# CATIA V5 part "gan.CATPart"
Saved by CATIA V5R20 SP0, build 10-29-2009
Part number: 杆
Bounding box of the stored display mesh (mm): x -8.5 to 10, y -89.091 to 471.474, z -537.91 to 111.108
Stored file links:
  E:\3D工程制图作业\Part1.CATPart
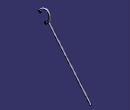
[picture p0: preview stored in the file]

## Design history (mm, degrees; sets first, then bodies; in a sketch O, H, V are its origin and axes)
Body1 (main body)
  Sketch1 on yz-plane, origin (0, 0, 0), H (0, 1, 0), V (0, 0, 1)
    line L1 (16.6642, 5.1613) -> (464.9558, -532.4581)
    point P2 (464.9558, -532.4581)
    spline S1 through (16.6642, 5.1613) (28.9221, 65.5082) (8.9158, 97.5942) (-34.5762, 97.5941) (-72.8491, 60.3051)
    point P3 (16.6642, 5.1613)
    length L1 = 700
    coincidence: P3 L1
  Plane1: type Normal, Curve Sketch1, RefPoint Sketch1.P2
  Sketch2 on Plane1, origin (0, 452.5874, -542.7714), H (1, 0, 0), V (0, 0.768, 0.6404)
    circle A1 centre (0, 16.0904) radius 8.5
    point P1 (0, 16.0904)
    radius A1 = 8.5
    coincidence: P1 V
  Rib1: profile Sketch2, centre curve Sketch1
  Sketch3 on yz-plane, origin (0, 0, 0), H (0, 1, 0), V (0, 0, 1)
    line L1 (8.417, 8.7931) -> (-16.6905, -10.3475)
    line L2 (-16.6905, -10.3475) -> (-6.2153, -24.0883)
    line L3 (-6.2153, -24.0883) -> (18.8922, -4.9476)
    line L4 (18.8922, -4.9476) -> (8.417, 8.7931)
    perpendicularity: L2 L1
    parallelism: L4 L2
  Pad1: profile Sketch3, direction (1, 0, 0), length 10
  Sketch4 on yz-plane, origin (0, 0, 0), H (0, 1, 0), V (0, 0, 1)
    arc A1 centre (-76.2659, 50.9664) radius 12.9848 from (-80.4951, 63.2431) to (-64.9039, 57.252) ccw
    line L1 (-64.9039, 57.252) -> (-80.4951, 63.2431)
    reference projected line E1 (-64.902, 57.2513) -> (-80.7708, 63.3491) from edge [face of Rib1 | face of Rib1]
    angle E1 L1 = 0
  Pad2: profile Sketch4, direction (-1, 0, 0), length 2
  Sketch5 on start face of Pad1, origin (0, -1.46, -11.1099), H (0, 1, 0), V (0, 0, -1)
    point P1 (0, 0)
  Hole1: placed by Sketch5, at (0, -1.46, -11.1099) direction (1, 0, 0), diameter 10, depth 10
  Sketch6 on start face of Pad2, origin (0, 0, 0), H (0, 1, 0), V (0, 0, 1)
    circle A1 centre (-75.8886, 45.0091) radius 5
    radius A1 = 5
  Pad3: profile Sketch6, direction (1, 0, 0), length 4
  Sketch7 on end face of Pad2, origin (-2, 0, 0), H (0, -1, 0), V (0, 0, 1)
    arc A1 centre (-37.7091, 41.5824) radius 12.9848 from (-40.8224, 54.1884) to (-25.0606, 44.5185) ccw
    line L1 (-25.0606, 44.5185) -> (-40.8224, 54.1884)
  Pad4: profile Sketch7, direction (-1, 0, 0), length 2, mirrored extent
Current feature: Pad3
